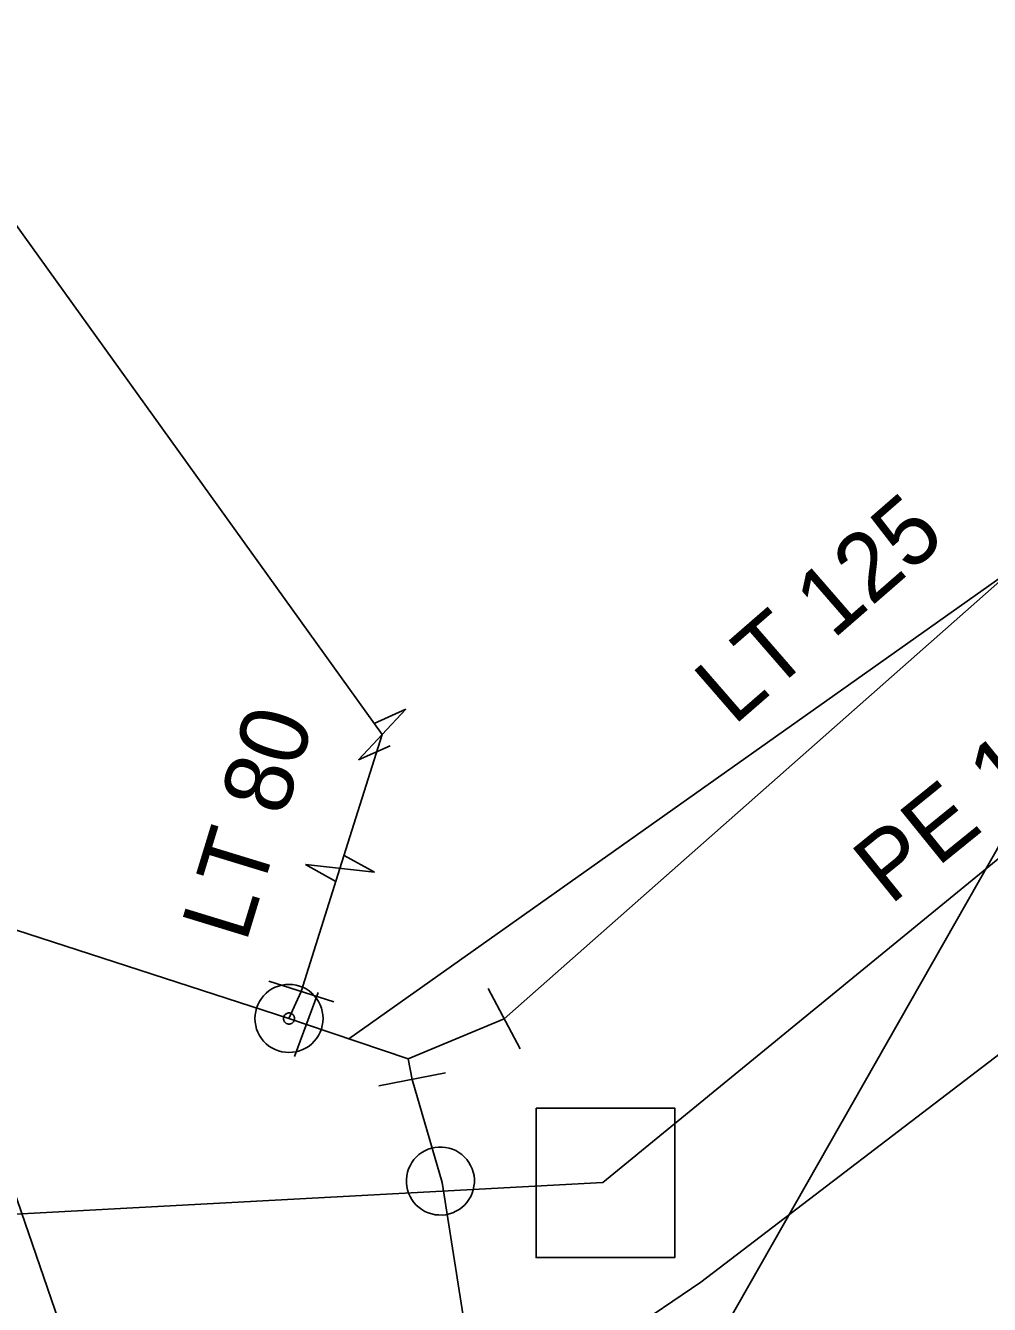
# Model space of a CAD drawing. Extents: x -743072 to -742584, y -978827 to -978325.
# Drawn here: x -742804.58 to -742790.44, y -978604.46 to -978585.7 of the extents above; entities that cross this region are included whole.
import ezdxf

# ---------------------------------------------------------------- set-up
doc = ezdxf.new("R2010")
doc.units = 0
for name, color, linetype in [('IS_CEZ_NN_nadz', 7, 'Continuous'), ('IS_GasNet_ochr pasmo', 7, 'Continuous'), ('IS_popis_ScVK', 7, 'Continuous'), ('IS_ScVK_Kanal_dest', 7, 'Continuous'), ('IS_ScVK_Kanal_šachty', 7, 'Continuous'), ('IS_ScVK_Vodovod', 7, 'Continuous'), ('IS_ScVK_Vodovod_vytyč', 7, 'Continuous')]:
    doc.layers.add(name, color=color, linetype=linetype)

msp = doc.modelspace()

# ---------------------------------------------------------------- linework, layer by layer
at = {"layer": 'IS_CEZ_NN_nadz'}
msp.add_lwpolyline([(-742776.65, -978574.74), (-742783.51, -978585.81), (-742799.53, -978613.952)], dxfattribs=at)
at = {"layer": 'IS_GasNet_ochr pasmo'}
msp.add_lwpolyline([(-742798.985, -978621.533), (-742801.529, -978619.869), (-742803.905, -978611.408), (-742808.036, -978599.405), (-742808.171, -978599.014), (-742807.807, -978598.269), (-742807.415, -978598.134), (-742807.024, -978597.999), (-742806.279, -978598.363), (-742806.144, -978598.755), (-742801.995, -978610.812)], close=True, dxfattribs=at)
at = {"layer": 'IS_ScVK_Kanal_dest'}
for points in [[(-742780.82, -978590.157), (-742796.109, -978602.67)], [(-742836.89, -978635.23), (-742836.829, -978632.584), (-742794.674, -978604.136), (-742784.548, -978596.4), (-742778.303, -978601.806), (-742769.218, -978607.658), (-742757.236, -978613.629), (-742748.697, -978616.71), (-742737.016, -978619.72), (-742706.897, -978621.455), (-742694.704, -978621.477), (-742669.125, -978621.524), (-742647.601, -978624.622), (-742643.224, -978625.196), (-742627.191, -978628.893), (-742614.992, -978632.031), (-742608.58, -978633.224), (-742593.026, -978634.809), (-742583.863, -978635.543)], [(-742800.716, -978600.266), (-742800.535, -978599.87)], [(-742800.461, -978600.352), (-742800.716, -978600.266)], [(-742798.91, -978601.16), (-742798.969, -978600.856)], [(-742796.109, -978602.67), (-742821.52, -978604.039)]]:
    msp.add_lwpolyline(points, dxfattribs=at)
at = {"layer": 'IS_ScVK_Kanal_šachty'}
msp.add_lwpolyline([(-742797.089, -978601.58), (-742795.056, -978601.58), (-742795.056, -978603.773), (-742797.089, -978603.773), (-742797.089, -978601.58)], dxfattribs=at)
at = {"layer": 'IS_ScVK_Vodovod'}
for points in [[(-742799.35, -978596.101), (-742827.12, -978557.465), (-742850.787, -978530.098)], [(-742915.09, -978596.84), (-742888.226, -978574.263), (-742883.014, -978569.821), (-742878.561, -978571.932), (-742836.693, -978590.888), (-742816.409, -978595.182), (-742800.716, -978600.266)], [(-742785.02, -978589.205), (-742797.559, -978600.27)], [(-742799.698, -978596.472), (-742799.001, -978595.729)], [(-742799.001, -978595.729), (-742799.467, -978595.937)], [(-742799.35, -978596.101), (-742799.968, -978598.065)], [(-742799.698, -978596.472), (-742799.232, -978596.264)], [(-742799.461, -978598.121), (-742799.907, -978597.873)], [(-742800.535, -978599.87), (-742799.968, -978598.065)], [(-742800.474, -978598.008), (-742799.461, -978598.121)], [(-742800.474, -978598.008), (-742800.028, -978598.256)], [(-742800.216, -978600.266), (-742800.219, -978600.213), (-742800.227, -978600.161), (-742800.241, -978600.112), (-742800.259, -978600.063), (-742800.283, -978600.016), (-742800.312, -978599.972), (-742800.345, -978599.931), (-742800.382, -978599.894), (-742800.422, -978599.862), (-742800.466, -978599.833), (-742800.513, -978599.808), (-742800.562, -978599.791), (-742800.612, -978599.777), (-742800.664, -978599.769), (-742800.716, -978599.766), (-742800.768, -978599.769), (-742800.82, -978599.777), (-742800.871, -978599.791), (-742800.919, -978599.808), (-742800.966, -978599.833), (-742801.01, -978599.862), (-742801.051, -978599.894), (-742801.088, -978599.931), (-742801.121, -978599.972), (-742801.149, -978600.016), (-742801.173, -978600.063), (-742801.192, -978600.112), (-742801.205, -978600.161), (-742801.213, -978600.213), (-742801.216, -978600.266), (-742801.213, -978600.318), (-742801.205, -978600.37), (-742801.192, -978600.421), (-742801.173, -978600.468), (-742801.149, -978600.516), (-742801.121, -978600.559), (-742801.088, -978600.6), (-742801.051, -978600.637), (-742801.01, -978600.671), (-742800.966, -978600.698), (-742800.919, -978600.723), (-742800.871, -978600.742), (-742800.82, -978600.754), (-742800.768, -978600.762), (-742800.716, -978600.766), (-742800.664, -978600.762), (-742800.612, -978600.754), (-742800.562, -978600.742), (-742800.513, -978600.723), (-742800.466, -978600.698), (-742800.422, -978600.671), (-742800.382, -978600.637), (-742800.345, -978600.6), (-742800.312, -978600.559), (-742800.283, -978600.516), (-742800.259, -978600.468), (-742800.241, -978600.421), (-742800.227, -978600.37), (-742800.219, -978600.318), (-742800.216, -978600.266)], [(-742801.012, -978599.72), (-742800.058, -978600.02)], [(-742800.633, -978600.821), (-742800.287, -978599.883)], [(-742797.794, -978599.828), (-742797.324, -978600.711)], [(-742800.634, -978600.266), (-742800.634, -978600.257), (-742800.636, -978600.249), (-742800.638, -978600.24), (-742800.641, -978600.232), (-742800.645, -978600.225), (-742800.65, -978600.218), (-742800.655, -978600.21), (-742800.661, -978600.205), (-742800.668, -978600.2), (-742800.675, -978600.195), (-742800.683, -978600.191), (-742800.691, -978600.188), (-742800.699, -978600.186), (-742800.707, -978600.183), (-742800.716, -978600.183), (-742800.725, -978600.183), (-742800.733, -978600.186), (-742800.741, -978600.188), (-742800.749, -978600.191), (-742800.757, -978600.195), (-742800.764, -978600.2), (-742800.771, -978600.205), (-742800.777, -978600.21), (-742800.783, -978600.218), (-742800.787, -978600.225), (-742800.791, -978600.232), (-742800.794, -978600.24), (-742800.796, -978600.249), (-742800.798, -978600.257), (-742800.798, -978600.266), (-742800.798, -978600.274), (-742800.796, -978600.282), (-742800.794, -978600.291), (-742800.791, -978600.299), (-742800.787, -978600.306), (-742800.783, -978600.313), (-742800.777, -978600.321), (-742800.771, -978600.326), (-742800.764, -978600.333), (-742800.757, -978600.337), (-742800.749, -978600.34), (-742800.741, -978600.343), (-742800.733, -978600.345), (-742800.725, -978600.348), (-742800.716, -978600.348), (-742800.707, -978600.348), (-742800.699, -978600.345), (-742800.691, -978600.343), (-742800.683, -978600.34), (-742800.675, -978600.337), (-742800.668, -978600.333), (-742800.661, -978600.326), (-742800.655, -978600.321), (-742800.65, -978600.313), (-742800.645, -978600.306), (-742800.641, -978600.299), (-742800.638, -978600.291), (-742800.636, -978600.282), (-742800.634, -978600.274), (-742800.634, -978600.266)], [(-742797.559, -978600.27), (-742798.969, -978600.856), (-742800.461, -978600.352)], [(-742799.4, -978601.256), (-742798.419, -978601.064)], [(-742798.91, -978601.16), (-742798.469, -978602.67)], [(-742798.723, -978602.205), (-742798.768, -978602.231)], [(-742798.723, -978602.205), (-742798.768, -978602.231)], [(-742798.675, -978602.184), (-742798.723, -978602.205)], [(-742798.675, -978602.184), (-742798.723, -978602.205)], [(-742798.625, -978602.167), (-742798.675, -978602.184)], [(-742798.625, -978602.167), (-742798.675, -978602.184)], [(-742798.574, -978602.156), (-742798.625, -978602.167)], [(-742798.574, -978602.156), (-742798.625, -978602.167)], [(-742798.522, -978602.152), (-742798.574, -978602.156)], [(-742798.522, -978602.152), (-742798.574, -978602.156)], [(-742798.47, -978602.151), (-742798.522, -978602.152)], [(-742798.47, -978602.151), (-742798.522, -978602.152)], [(-742798.417, -978602.156), (-742798.47, -978602.151)], [(-742798.417, -978602.156), (-742798.47, -978602.151)], [(-742798.367, -978602.167), (-742798.417, -978602.156)], [(-742798.367, -978602.167), (-742798.417, -978602.156)], [(-742798.316, -978602.183), (-742798.367, -978602.167)], [(-742798.316, -978602.183), (-742798.367, -978602.167)], [(-742798.269, -978602.203), (-742798.316, -978602.183)], [(-742798.269, -978602.203), (-742798.316, -978602.183)], [(-742798.224, -978602.23), (-742798.269, -978602.203)], [(-742798.224, -978602.23), (-742798.269, -978602.203)], [(-742798.915, -978602.379), (-742798.94, -978602.425)], [(-742798.915, -978602.379), (-742798.94, -978602.425)], [(-742798.884, -978602.336), (-742798.915, -978602.379)], [(-742798.884, -978602.336), (-742798.915, -978602.379)], [(-742798.848, -978602.298), (-742798.884, -978602.336)], [(-742798.848, -978602.298), (-742798.884, -978602.336)], [(-742798.809, -978602.262), (-742798.848, -978602.298)], [(-742798.809, -978602.262), (-742798.848, -978602.298)], [(-742798.768, -978602.231), (-742798.809, -978602.262)], [(-742798.768, -978602.231), (-742798.809, -978602.262)], [(-742798.181, -978602.261), (-742798.224, -978602.23)], [(-742798.181, -978602.261), (-742798.224, -978602.23)], [(-742798.143, -978602.295), (-742798.181, -978602.261)], [(-742798.143, -978602.295), (-742798.181, -978602.261)], [(-742798.106, -978602.334), (-742798.143, -978602.295)], [(-742798.106, -978602.334), (-742798.143, -978602.295)], [(-742798.075, -978602.377), (-742798.106, -978602.334)], [(-742798.075, -978602.377), (-742798.106, -978602.334)], [(-742798.05, -978602.421), (-742798.075, -978602.377)], [(-742798.05, -978602.421), (-742798.075, -978602.377)], [(-742798.989, -978602.572), (-742798.993, -978602.626)], [(-742798.989, -978602.572), (-742798.993, -978602.626)], [(-742798.977, -978602.522), (-742798.989, -978602.572)], [(-742798.977, -978602.522), (-742798.989, -978602.572)], [(-742798.962, -978602.471), (-742798.977, -978602.522)], [(-742798.962, -978602.471), (-742798.977, -978602.522)], [(-742798.94, -978602.425), (-742798.962, -978602.471)], [(-742798.94, -978602.425), (-742798.962, -978602.471)], [(-742798.028, -978602.47), (-742798.05, -978602.421)], [(-742798.028, -978602.47), (-742798.05, -978602.421)], [(-742798.012, -978602.518), (-742798.028, -978602.47)], [(-742798.012, -978602.518), (-742798.028, -978602.47)], [(-742798, -978602.571), (-742798.012, -978602.518)], [(-742798, -978602.571), (-742798.012, -978602.518)], [(-742797.996, -978602.623), (-742798, -978602.571)], [(-742797.996, -978602.623), (-742798, -978602.571)], [(-742798.993, -978602.626), (-742798.993, -978602.677)], [(-742798.993, -978602.626), (-742798.993, -978602.677)], [(-742798.993, -978602.677), (-742798.988, -978602.729)], [(-742798.993, -978602.677), (-742798.988, -978602.729)], [(-742798.988, -978602.729), (-742798.976, -978602.78)], [(-742798.988, -978602.729), (-742798.976, -978602.78)], [(-742798.976, -978602.78), (-742798.961, -978602.83)], [(-742798.976, -978602.78), (-742798.961, -978602.83)], [(-742798.469, -978602.67), (-742792.475, -978640.717)], [(-742798.028, -978602.828), (-742798.011, -978602.778)], [(-742798.028, -978602.828), (-742798.011, -978602.778)], [(-742798.011, -978602.778), (-742798.001, -978602.726)], [(-742798.011, -978602.778), (-742798.001, -978602.726)], [(-742798.001, -978602.726), (-742797.995, -978602.675)], [(-742798.001, -978602.726), (-742797.995, -978602.675)], [(-742797.995, -978602.675), (-742797.996, -978602.623)], [(-742797.995, -978602.675), (-742797.996, -978602.623)], [(-742798.961, -978602.83), (-742798.939, -978602.878)], [(-742798.961, -978602.83), (-742798.939, -978602.878)], [(-742798.939, -978602.878), (-742798.912, -978602.923)], [(-742798.939, -978602.878), (-742798.912, -978602.923)], [(-742798.912, -978602.923), (-742798.882, -978602.966)], [(-742798.912, -978602.923), (-742798.882, -978602.966)], [(-742798.882, -978602.966), (-742798.848, -978603.004)], [(-742798.882, -978602.966), (-742798.848, -978603.004)], [(-742798.14, -978603.002), (-742798.106, -978602.963)], [(-742798.14, -978603.002), (-742798.106, -978602.963)], [(-742798.106, -978602.963), (-742798.075, -978602.921)], [(-742798.106, -978602.963), (-742798.075, -978602.921)], [(-742798.075, -978602.921), (-742798.049, -978602.876)], [(-742798.075, -978602.921), (-742798.049, -978602.876)], [(-742798.049, -978602.876), (-742798.028, -978602.828)], [(-742798.049, -978602.876), (-742798.028, -978602.828)], [(-742798.848, -978603.004), (-742798.807, -978603.039)], [(-742798.848, -978603.004), (-742798.807, -978603.039)], [(-742798.807, -978603.039), (-742798.766, -978603.07)], [(-742798.807, -978603.039), (-742798.766, -978603.07)], [(-742798.766, -978603.07), (-742798.721, -978603.095)], [(-742798.766, -978603.07), (-742798.721, -978603.095)], [(-742798.721, -978603.095), (-742798.672, -978603.118)], [(-742798.721, -978603.095), (-742798.672, -978603.118)], [(-742798.672, -978603.118), (-742798.622, -978603.133)], [(-742798.672, -978603.118), (-742798.622, -978603.133)], [(-742798.622, -978603.133), (-742798.571, -978603.144)], [(-742798.622, -978603.133), (-742798.571, -978603.144)], [(-742798.571, -978603.144), (-742798.519, -978603.148)], [(-742798.571, -978603.144), (-742798.519, -978603.148)], [(-742798.519, -978603.148), (-742798.467, -978603.149)], [(-742798.519, -978603.148), (-742798.467, -978603.149)], [(-742798.467, -978603.149), (-742798.415, -978603.144)], [(-742798.467, -978603.149), (-742798.415, -978603.144)], [(-742798.415, -978603.144), (-742798.363, -978603.133)], [(-742798.415, -978603.144), (-742798.363, -978603.133)], [(-742798.363, -978603.133), (-742798.313, -978603.116)], [(-742798.363, -978603.133), (-742798.313, -978603.116)], [(-742798.313, -978603.116), (-742798.267, -978603.094)], [(-742798.313, -978603.116), (-742798.267, -978603.094)], [(-742798.267, -978603.094), (-742798.221, -978603.068)], [(-742798.267, -978603.094), (-742798.221, -978603.068)], [(-742798.221, -978603.068), (-742798.179, -978603.038)], [(-742798.221, -978603.068), (-742798.179, -978603.038)], [(-742798.179, -978603.038), (-742798.14, -978603.002)], [(-742798.179, -978603.038), (-742798.14, -978603.002)]]:
    msp.add_lwpolyline(points, dxfattribs=at)
at = {"layer": 'IS_ScVK_Vodovod_vytyč'}
msp.add_line((-742784.508, -978589.716), (-742799.838, -978600.562), dxfattribs=at)

# ---------------------------------------------------------------- texts
at = {"layer": 'IS_popis_ScVK'}
for s, rotation, p in [('LT 125', 41, (-742794.191, -978595.983)), ('PE 110', 39, (-742791.894, -978598.616)), ('LT 80 ', 73, (-742801.348, -978599.171))]:
    msp.add_text(s, height=1, rotation=rotation, dxfattribs=at).set_placement(p)

doc.saveas('drawing.dxf')
